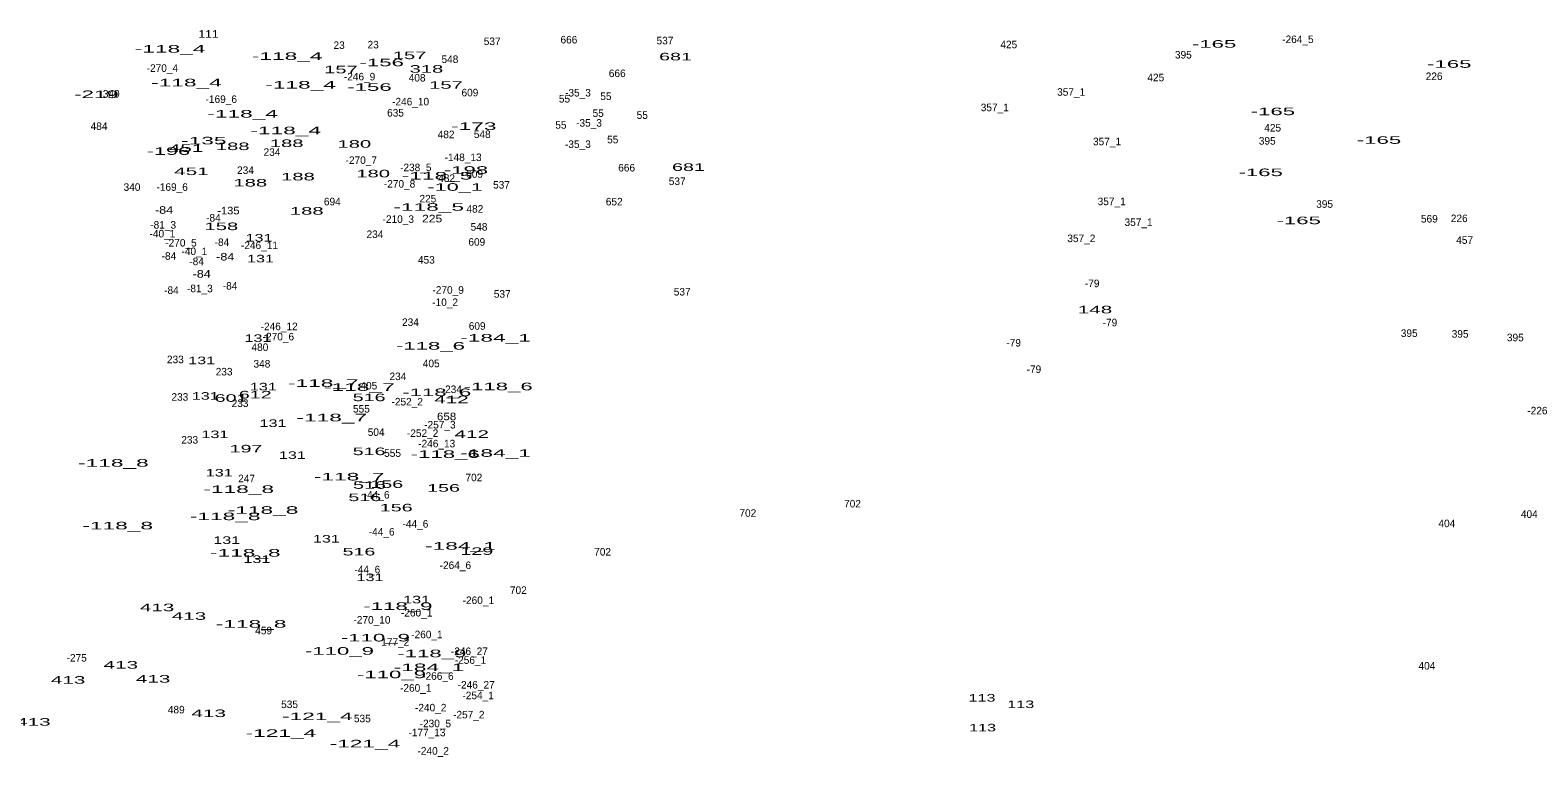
# Model space of a CAD drawing. Extents: x -658595 to -655205, y -1004347 to -1000147.
# Drawn here: x -656879 to -656080, y -1001203 to -1000817 of the extents above; entities that cross this region are included whole.
import ezdxf
from ezdxf.enums import TextEntityAlignment as Align

# ---------------------------------------------------------------- set-up
doc = ezdxf.new("R2010")
doc.units = 0
doc.header["$LTSCALE"] = 1.6
doc.layers.add('24', color=7, linetype='Continuous')

msp = doc.modelspace()

# ---------------------------------------------------------------- texts
at = {"layer": '24'}
for s, width, p in [('111', 1.2, (-656784.77, -1000821.28)), ('-118_4', 2.25, (-656805.113, -1000829.2)), ('-165', 2.2, (-656251.355, -1000826.58)), ('-118_4', 2.25, (-656743.023, -1000833.04)), ('-156', 2.2, (-656692.885, -1000836.4)), ('157', 2, (-656678.093, -1000832.64)), ('681', 1.95, (-656537.023, -1000833.3)), ('-165', 2.2, (-656126.595, -1000837.21)), ('157', 2, (-656714.513, -1000840.16)), ('318', 2, (-656669.167, -1000839.83)), ('-219', 2.2, (-656844.195, -1000853.29)), ('-118_4', 2.25, (-656796.463, -1000847.08)), ('-118_4', 2.25, (-656735.923, -1000848.24)), ('-156', 2.2, (-656699.365, -1000849.44)), ('157', 2, (-656658.793, -1000848.34)), ('-165', 2.2, (-656220.165, -1000862.35)), ('-118_4', 2.25, (-656766.673, -1000863.62)), ('-173', 2.25, (-656644.035, -1000870.19)), ('-135', 2.25, (-656787.251, -1000877.84)), ('-118_4', 2.25, (-656743.793, -1000872.46)), ('-165', 2.2, (-656163.865, -1000877.54)), ('-196', 2.15, (-656806.039, -1000883.39)), ('451', 2.05, (-656796.663, -1000881.8)), ('188', 2, (-656771.917, -1000880.86)), ('188', 2, (-656743.297, -1000879.25)), ('180', 2, (-656707.404, -1000879.61)), ('451', 2.05, (-656793.813, -1000894.11)), ('-198', 2.2, (-656648.185, -1000893.43)), ('681', 1.95, (-656530.173, -1000891.9)), ('188', 2, (-656762.597, -1000900.17)), ('188', 2, (-656737.307, -1000896.94)), ('180', 2, (-656697.424, -1000895.31)), ('-118_5', 2.25, (-656663.517, -1000896.48)), ('-10_1', 2.15, (-656653.944, -1000902.44)), ('-165', 2.2, (-656226.625, -1000894.66)), ('-84', 1.25, (-656808.34, -1000914.62)), ('-135', 1.1, (-656774.201, -1000914.94)), ('188', 2, (-656732.647, -1000915.11)), ('-118_5', 2.25, (-656667.937, -1000913.02)), ('158', 2, (-656777.937, -1000923.29)), ('225', 1.2, (-656666.14, -1000919.17)), ('-165', 2.2, (-656206.465, -1000920.16)), ('131', 1.6, (-656757.964, -1000929.37)), ('-84', 1.25, (-656775.88, -1000939.4)), ('131', 1.6, (-656757.194, -1000940.4)), ('-84', 1.25, (-656788.38, -1000948.52)), ('148', 2.05, (-656314.533, -1000967.42)), ('-184_1', 2.25, (-656632.503, -1000982.41)), ('131', 1.6, (-656758.534, -1000982.59)), ('-118_6', 2.2, (-656667.053, -1000986.66)), ('131', 1.6, (-656788.384, -1000994.38)), ('-118_7', 2.25, (-656723.883, -1001006.4)), ('131', 1.6, (-656786.484, -1001013.22)), ('601', 1.95, (-656772.799, -1001014.33)), ('612', 1.95, (-656759.973, -1001012.54)), ('131', 1.6, (-656755.674, -1001008.27)), ('-118_7', 2.25, (-656704.753, -1001008.52)), ('516', 1.95, (-656699.563, -1001013.98)), ('-118_6', 2.2, (-656663.693, -1001011.29)), ('-118_6', 2.2, (-656631.113, -1001008.2)), ('412', 2.05, (-656655.863, -1001015.06)), ('131', 1.6, (-656750.544, -1001027.68)), ('-118_7', 2.25, (-656719.363, -1001024.68)), ('658', 1.15, (-656658.48, -1001024.1)), ('131', 1.6, (-656781.354, -1001033.58)), ('412', 2.05, (-656645.123, -1001033.48)), ('197', 1.95, (-656764.867, -1001041.17)), ('131', 1.6, (-656740.274, -1001044.61)), ('516', 1.95, (-656699.563, -1001042.6)), ('-118_6', 2.2, (-656659.173, -1001044.07)), ('-184_1', 2.25, (-656632.503, -1001043.48)), ('-118_8', 2.25, (-656835.227, -1001048.72)), ('131', 1.6, (-656779.074, -1001053.93)), ('-118_7', 2.25, (-656710.133, -1001056.02)), ('516', 1.95, (-656699.373, -1001060.45)), ('156', 1.95, (-656690.213, -1001059.99)), ('156', 1.95, (-656660.073, -1001061.99)), ('-118_8', 2.25, (-656768.727, -1001062.65)), ('516', 1.95, (-656701.863, -1001066.98)), ('-118_8', 2.25, (-656775.927, -1001077.08)), ('-118_8', 2.25, (-656755.847, -1001073.71)), ('156', 1.95, (-656685.173, -1001072.44)), ('-118_8', 2.25, (-656832.927, -1001081.98)), ('131', 1.6, (-656775.074, -1001089.68)), ('131', 1.6, (-656722.204, -1001088.94)), ('-184_1', 2.25, (-656651.133, -1001092.75)), ('-118_8', 2.25, (-656765.257, -1001096.4)), ('131', 1.6, (-656759.104, -1001099.76)), ('516', 1.95, (-656704.943, -1001095.79)), ('129', 1.95, (-656642.433, -1001095.49)), ('131', 1.6, (-656699.074, -1001109.39)), ('413', 2.05, (-656812.053, -1001125.36)), ('-118_9', 2.2, (-656684.303, -1001124.67)), ('131', 1.6, (-656674.354, -1001121.19)), ('413', 2.05, (-656795.123, -1001129.93)), ('-118_8', 2.25, (-656762.167, -1001134.09)), ('-110_9', 2.2, (-656696.239, -1001141.39)), ('-110_9', 2.2, (-656715.319, -1001148.42)), ('-118_9', 2.2, (-656666.323, -1001149.76)), ('413', 2.05, (-656831.263, -1001155.8)), ('-184_1', 2.25, (-656667.813, -1001157.12)), ('413', 2.05, (-656859.213, -1001163.79)), ('413', 2.05, (-656814.143, -1001163.22)), ('-110_9', 2.2, (-656687.689, -1001160.89)), ('113', 1.6, (-656374.444, -1001173.29)), ('413', 2.05, (-656784.663, -1001181.49)), ('113', 1.6, (-656353.904, -1001176.72)), ('413', 2.05, (-656877.663, -1001186.05)), ('-121_4', 2.25, (-656727.043, -1001183.13)), ('113', 1.6, (-656374.164, -1001189.08)), ('-121_4', 2.25, (-656746.363, -1001191.98)), ('-121_4', 2.25, (-656701.773, -1001197.56))]:
    msp.add_text(s, height=4, dxfattribs=dict(at, width=width)).set_placement(p, align=Align.CENTER)
for s, p in [('23', (-656715.477, -1000827.25)), ('23', (-656697.417, -1000826.96)), ('537', (-656634.293, -1000825.18)), ('666', (-656593.593, -1000824.33)), ('537', (-656542.623, -1000824.8)), ('425', (-656360.251, -1000826.88)), ('-264_5', (-656206.892, -1000824.13)), ('548', (-656656.691, -1000834.7)), ('395', (-656267.673, -1000832.31)), ('-270_4', (-656809.226, -1000839.39)), ('-246_9', (-656704.628, -1000843.92)), ('408', (-656674.105, -1000844.51)), ('666', (-656567.953, -1000842.16)), ('425', (-656282.281, -1000844.38)), ('226', (-656134.643, -1000843.72)), ('340', (-656836.365, -1000853.02)), ('609', (-656646.092, -1000852.36)), ('-35_3', (-656588.782, -1000852.45)), ('55', (-656573.967, -1000854.32)), ('357_1', (-656327.174, -1000852.06)), ('-169_6', (-656777.982, -1000855.86)), ('-246_10', (-656677.569, -1000857.16)), ('55', (-656595.937, -1000855.66)), ('357_1', (-656367.684, -1000860.24)), ('484', (-656842.816, -1000870.19)), ('635', (-656685.563, -1000863.08)), ('55', (-656597.837, -1000869.54)), ('-35_3', (-656582.932, -1000868.43)), ('55', (-656578.057, -1000863.27)), ('55', (-656554.667, -1000864.31)), ('482', (-656658.741, -1000874.58)), ('548', (-656639.561, -1000874.47)), ('55', (-656570.357, -1000877.25)), ('357_1', (-656308.154, -1000878.31)), ('395', (-656223.173, -1000877.97)), ('425', (-656220.281, -1000871.02)), ('234', (-656751.081, -1000883.91)), ('-35_3', (-656588.832, -1000879.75)), ('234', (-656765.151, -1000893.52)), ('-270_7', (-656703.718, -1000888.22)), ('-238_5', (-656674.812, -1000892.06)), ('-148_13', (-656649.703, -1000886.7)), ('666', (-656562.953, -1000892.21)), ('340', (-656825.335, -1000902.48)), ('-169_6', (-656804.042, -1000902.46)), ('-270_8', (-656683.412, -1000900.78)), ('482', (-656658.451, -1000897.72)), ('609', (-656643.592, -1000895.54)), ('537', (-656629.353, -1000901.27)), ('537', (-656536.153, -1000899.37)), ('694', (-656719.073, -1000910.15)), ('225', (-656668.407, -1000908.62)), ('652', (-656569.553, -1000910.2)), ('357_1', (-656305.684, -1000910.08)), ('482', (-656643.471, -1000914.05)), ('395', (-656192.743, -1000911.46)), ('-81_3', (-656808.816, -1000922.52)), ('-84', (-656782.149, -1000918.75)), ('-210_3', (-656684.1, -1000919.46)), ('548', (-656641.271, -1000923.56)), ('357_1', (-656291.414, -1000921.12)), ('569', (-656137.168, -1000919.29)), ('226', (-656121.333, -1000919.06)), ('-40_1', (-656809.194, -1000927.17)), ('-270_5', (-656799.362, -1000932)), ('-84', (-656777.629, -1000931.71)), ('-246_11', (-656757.709, -1000933.36)), ('234', (-656696.451, -1000927.49)), ('609', (-656642.442, -1000931.57)), ('357_2', (-656321.76, -1000929.66)), ('457', (-656118.457, -1000930.59)), ('-84', (-656805.759, -1000939.02)), ('-40_1', (-656792.234, -1000936.52)), ('-84', (-656791.079, -1000941.89)), ('453', (-656669.201, -1000941.05)), ('-84', (-656804.419, -1000957.17)), ('-81_3', (-656789.336, -1000956.23)), ('-84', (-656773.309, -1000954.86)), ('-270_9', (-656657.647, -1000957.03)), ('537', (-656533.493, -1000957.97)), ('-79', (-656316.015, -1000953.54)), ('-10_2', (-656659.24, -1000963.55)), ('537', (-656628.963, -1000959.11)), ('234', (-656677.631, -1000974.1)), ('-79', (-656306.605, -1000974.28)), ('-246_12', (-656747.285, -1000976.36)), ('-270_6', (-656747.687, -1000981.78)), ('609', (-656642.252, -1000976.13)), ('395', (-656147.863, -1000979.95)), ('395', (-656120.853, -1000980.33)), ('395', (-656091.573, -1000982.23)), ('480', (-656757.495, -1000987.37)), ('-79', (-656357.675, -1000985.03)), ('233', (-656802.337, -1000993.86)), ('348', (-656756.421, -1000996.17)), ('405', (-656666.625, -1000995.99)), ('233', (-656776.477, -1001000.35)), ('234', (-656684.281, -1001002.83)), ('-79', (-656346.925, -1000999.05)), ('233', (-656799.957, -1001013.76)), ('405', (-656699.715, -1001007.79)), ('234', (-656654.801, -1001009.68)), ('233', (-656768.017, -1001017.09)), ('555', (-656703.657, -1001020.04)), ('-252_2', (-656679.362, -1001016.27)), ('-226_9', (-656076.863, -1001020.98)), ('-257_3', (-656662.028, -1001028.48)), ('233', (-656794.727, -1001036.49)), ('504', (-656695.835, -1001032.41)), ('-252_2', (-656671.192, -1001032.97)), ('-246_13', (-656663.715, -1001038.48)), ('555', (-656687.117, -1001043.52)), ('247', (-656764.557, -1001057)), ('702', (-656643.987, -1001056.46)), ('-44_6', (-656695.556, -1001065.62)), ('702', (-656443.157, -1001070.35)), ('702', (-656498.687, -1001075.3)), ('404', (-656084.15, -1001075.87)), ('-44_6', (-656692.896, -1001085.24)), ('-44_6', (-656674.996, -1001081.05)), ('404', (-656127.89, -1001080.82)), ('702', (-656575.707, -1001095.84)), ('-44_6', (-656700.506, -1001105.24)), ('-264_6', (-656653.818, -1001102.99)), ('702', (-656620.407, -1001116.2)), ('-260_1', (-656641.626, -1001121.55)), ('-270_10', (-656698.049, -1001131.95)), ('-260_1', (-656674.346, -1001128.17)), ('459', (-656755.537, -1001137.6)), ('-260_1', (-656668.886, -1001139.7)), ('177_2', (-656685.71, -1001143.66)), ('-246_27', (-656646.377, -1001148.6)), ('-275', (-656854.671, -1001152.07)), ('-256_1', (-656645.802, -1001153.26)), ('404', (-656138.47, -1001156.3)), ('-266_6', (-656663.088, -1001161.74)), ('-246_27', (-656642.767, -1001166.39)), ('-260_1', (-656674.826, -1001168.03)), ('-254_1', (-656641.74, -1001172.02)), ('489', (-656801.857, -1001179.55)), ('535', (-656741.767, -1001176.73)), ('-240_2', (-656666.901, -1001178.49)), ('-257_2', (-656646.688, -1001182.19)), ('535', (-656703.157, -1001184.24)), ('-230_5', (-656664.426, -1001186.89)), ('-177_13', (-656668.88, -1001191.69)), ('-240_2', (-656665.571, -1001201.42))]:
    msp.add_text(s, height=4, dxfattribs=at).set_placement(p, align=Align.CENTER)

doc.saveas('drawing.dxf')
